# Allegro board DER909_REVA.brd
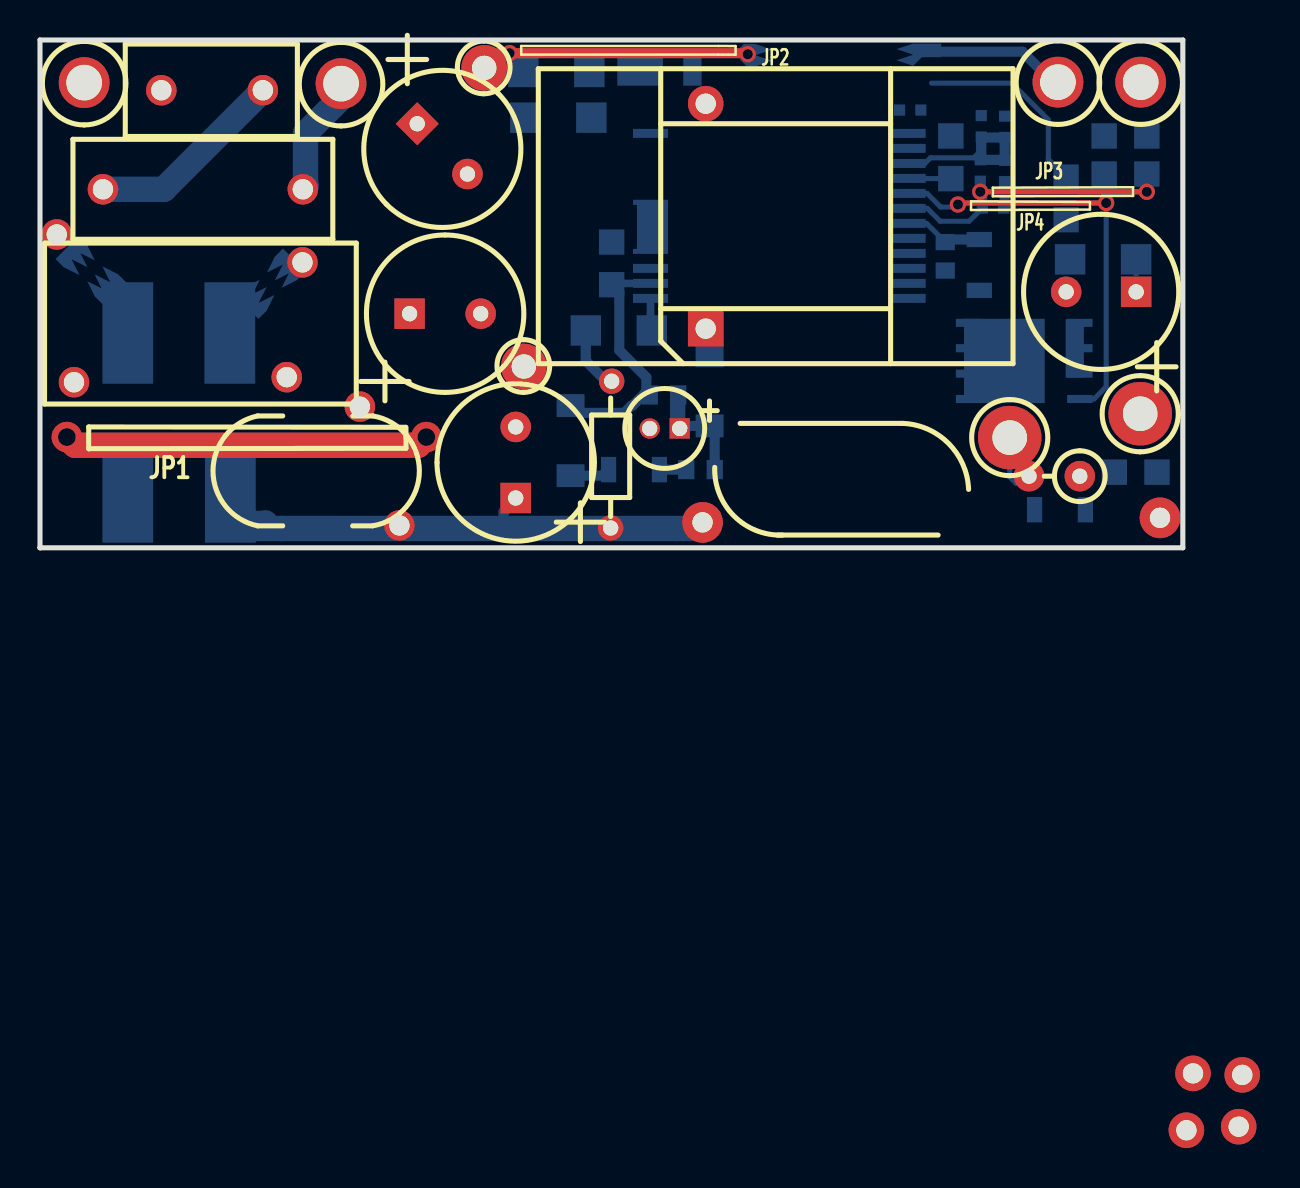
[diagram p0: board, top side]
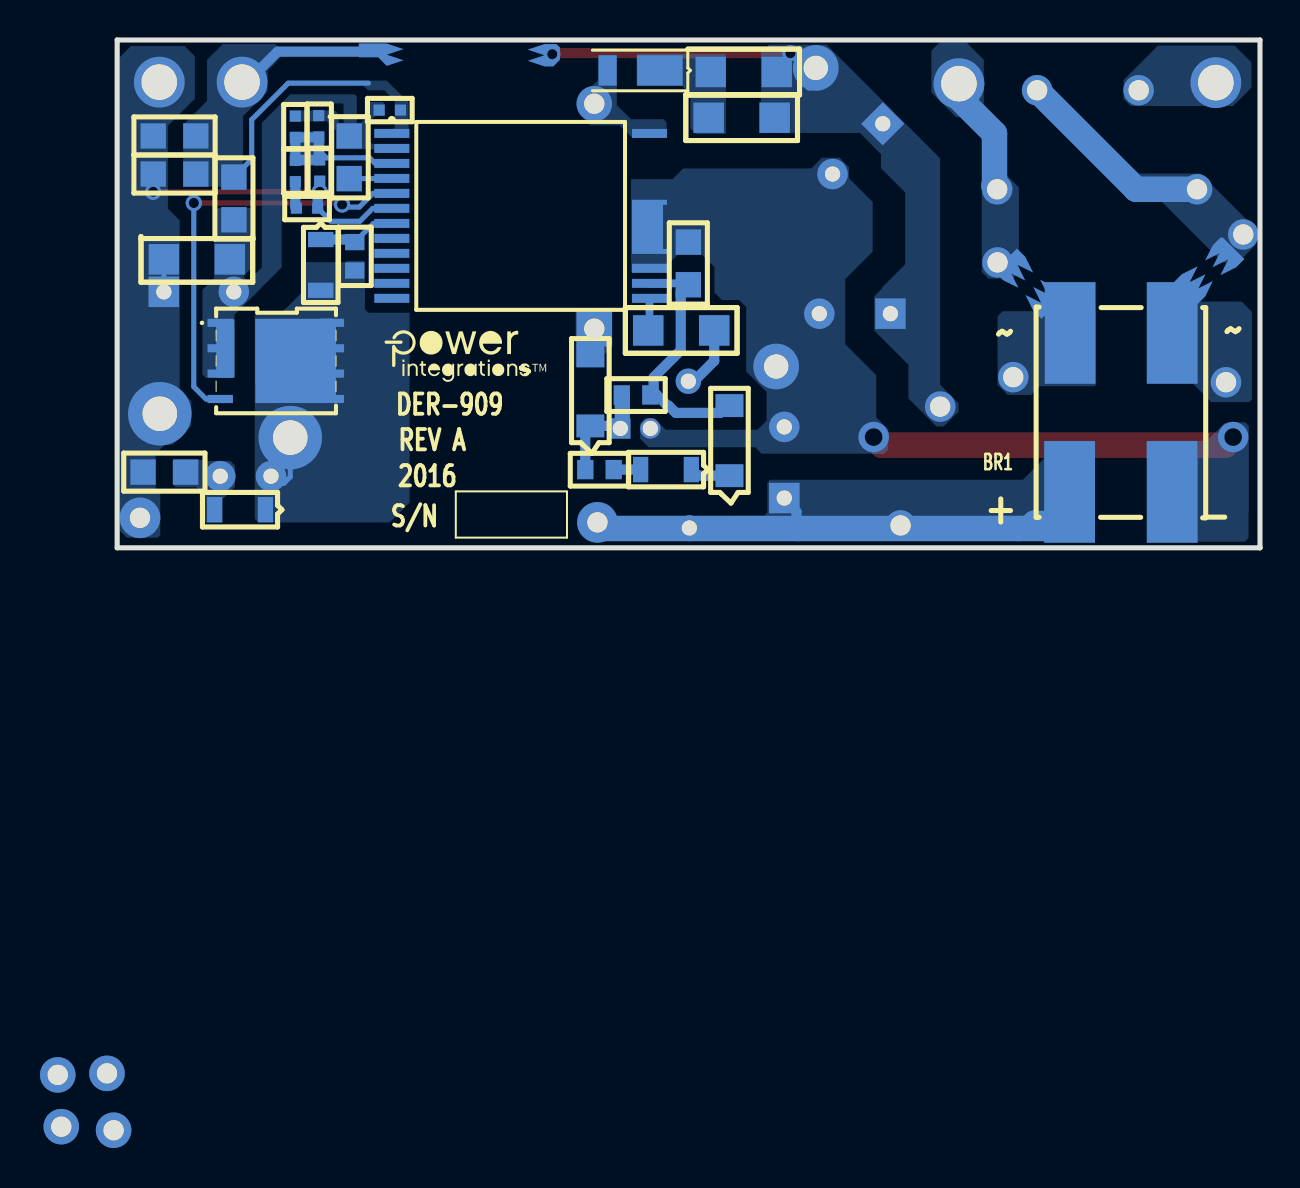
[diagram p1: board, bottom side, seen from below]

Outline 57.18 x 25.4 mm; copper layers: TOP, BOTTOM. Coordinates in mm from the lower left corner of the outline.
Outline path: 0,0 0,25.4 57.18,25.4 57.18,0 0,0 ; 0,0 0.03,0

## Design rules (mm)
constraint set DEFAULT: min track width 0.508

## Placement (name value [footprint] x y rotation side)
BR1  Z4DGP408L-HF  [PI_SM_D_Z4D]  9.5 2.74 0 bottom
C1  0.1 uF  [PINPXCAPRAD5X13X11P1MM040]  3.15 17.93 0 top
C2  22 uF  [PIPOLCAPCLYD320LS140030]  23.8 2.49 90 top
C3  22 uF  [PIPOLCAPCLYD320LS140030]  18.87 21.21 315 top
C4  22 uF  [PIPOLCAPCLYD320LS140030]  18.49 11.71 0 top
C5  2.2 nF  [PISMC1206]  24.28 21.51 0 bottom
C6  22 uf  [PIPOLCAP4P0X11P0XLS1P5D030]  32 5.97 180 top
C7  4.7 uF  [PISMC0805]  28.6 13.16 90 bottom
C8  1 nF  [PISMC0805]  53.75 3.78 0 bottom
C9  330 uF  [PIPOLCAPCYLD315LS138D030]  54.84 12.8 180 top
C10  2.2 uF  [PISMC0805]  45.57 20.6 270 bottom
C11  2.2 uF  [PISMC1206]  51.54 14.43 0 bottom
C12  1000 pF  [PISMR0402]  44.07 21.89 180 bottom
C13  330 pF  [PISMC0402]  47.09 20.55 90 bottom
C14  DNP  [PISMC0402]  48.26 18.31 90 bottom
C15  22 uF  [PISMC0805]  55.37 20.6 180 bottom
C16  22 uF  [PISMC0805]  55.37 18.69 180 bottom
C17  680 pF  [PINPCAPRAD394X275394030]  34.98 4.75 0 top
D1  DFLR1800-7  [PISMDDFLR120012]  30 23.88 180 bottom
D2  UFM12PL-TP  [PI_SM_SOD-123_12]  33.5 6.1 90 bottom
D3  BAV19WS  [PISMSOD323]  28.45 3.91 0 bottom
D4  BAV19WS  [PISMSOD323]  49.76 1.9 0 bottom
D5  BAV19WS  [PISMSOD323]  46.99 15.42 270 bottom
F1  3.15 A  [PI_RST_MICROFUSE]  6.07 22.89 0 top
FL1  Hole_70mils  [PI_HOLE_70MIL]  55.04 6.68 0 top
FL2  Hole_70mils  [PI_HOLE_70MIL]  48.51 5.49 0 top
FL3  Hole_50mils  [PI_HOLE_50MIL]  24.21 9.07 0 top
FL4  Hole_50mils  [PI_HOLE_50MIL]  22.23 24 0 top
L2  10 uH  [PI2P10P5X6P5X5P0LSD60]  13.89 1.35 90 top
L3  10 mH  [PI_IND_4P_590X295LS394X177D060]  3.05 13.44 180 top
NOREF  -  []  0 25.4 0 top
NOREF#2  -  []  -231.19 -154.89 0 top
NOREF#3  -  []  0.08 -0.03 90 top
NOREF#4  -  []  -153.38 44.12 0 top
NOREF#5  -  []  44.35 10.77 180 bottom
Q1  AON6220  [PISMPQFN5X6B]  52.02 11.25 270 bottom
R1  2 M  [PI18WVRESD80LS100D030]  28.6 8.33 270 top
R2  1.80 M  [PISMR1206]  30.61 10.87 180 bottom
R3  330 k  [PISMR1206]  24.18 23.8 0 bottom
R4  5.6 k  [PISMR0603]  31.93 7.65 180 bottom
R5  47  [PISMR0603]  33.76 3.91 180 bottom
R6  5.1  [PI14WVRESD100LS100D030]  52.02 3.58 180 top
R7  300  [PISMR0603]  45.29 13.87 90 bottom
R8  169.0 k  [PISMR0402]  47.04 18.34 90 bottom
R9  DNP  [PISMR0402]  47.14 16.99 0 bottom
R10  11.3 k  [PISMR0402]  48.26 21.59 270 bottom
R11  0.013  [PISMR0805]  51.33 16.41 90 bottom
T1  ATQ23.7/14  [PI_BOBBIN_ATQ23_7_H_6P]  36.8 16.59 90 top
TP1  WHT  [PITPKEYSTONE125X125]  2.21 23.27 0 top
TP2  BLK  [PITPKEYSTONE125X125]  15.06 23.22 0 top
TP3  RED  [PITPKEYSTONE125X125]  55.07 23.29 0 top
TP4  BLK  [PITPKEYSTONE125X125]  50.93 23.29 0 top
U1  INN3679C-H606  [PI_IC_INSOP_24D]  43.43 20.73 180 bottom
VR1  MMSZ5242B-7-F  [PI_SM_SOD-123_12]  26.54 3.61 90 bottom

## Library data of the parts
BR1 = DISCRETE BRIDGE_+~~-: room: 1
C1 = CAP NP: alternate symbols: (pinpxcaprad5x13x11p1mm040h)
C2-C4 = CAP POL: alternate symbols: (pipolcapclyd320ls140d30h750)
C5 = CAP NP_0: room: 1
C6 = CAP POL: alternate symbols: (pipolcap4p0x12p5xls1p5d030h); room: 1
C7 C11 C15 C16 = CAP NP: room: 2
C8 = CAP NP: alternate symbols: (pismc0805_1); room: 2
C9 = CAP POL: alternate symbols: (pipolcapcyld315ls138d030h); room: 2
C10 = CAP NP_0: room: 2
C12-C14 = CAP NP: alternate symbols: (pismr0402_1); room: 2
C17 = CAP NP: alternate symbols: (pinpycaprad500x220ls400040); room: 2
D1-D3 = DIODE: room: 1
D4 = DIODE: room: 2
D5 = DIODE
F1 = FUSE: alternate symbols: (pirstmicrofusehoz); room: 1
FL1 FL2 = FlyingLead: room: 2
FL3 FL4 = FlyingLead
L2 = INDUCTOR
L3 = INDUCTOR_4P_revD
Q1 = FET_N_SGD_123_4_5678: room: 2
R1 = R: alternate symbols: (pi18wresd080ls300d030); room: 1
R2-R5 = R: room: 1
R6 = R: alternate symbols: (pi14wvresd100ls125d030,pi14wvresd100ls150d030,pi14wvresd100ls200d030,pi14wvresd100ls300d030,pi14wresd100ls400d030,pi14wresd100ls500d030); room: 2
R7 R8 R10 = R: room: 2
R9 = R: alternate symbols: (pismr0402_1); room: 2
R11 = R
T1 = BATQ23_7_6P/GENERIC
TP1-TP4 = TESTPOINT
U1 = Inno3EP_0
VR1 = DIODE_ZENER: room: 1

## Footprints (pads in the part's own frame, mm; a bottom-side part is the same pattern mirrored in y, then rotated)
PI2P10P5X6P5X5P0LSD60
  round 1.524 hole 1.016: 1(-0.229,-4.089) 2(5.715,-2.108)
PI14WVRESD100LS100D030
  round 1.524 hole 0.762: 1(0,0) 2(2.54,0)
PI18WVRESD80LS100D030
  round 1.27 hole 0.762: 1(0,0) 2(7.341,-0.051)
PI_BOBBIN_ATQ23_7_H_6P
  rect 1.778x1.778 hole 1.016: 1(-5.626,3.5)
  round 1.778 hole 1.016: 2(-42.951,-23.343) 3(-42.875,-20.879) 4(-45.542,-23.165) 5(-45.72,-20.549) 6(5.626,3.5)
PI_HOLE_50MIL
  round 2.286 hole 1.219: 1(0,0)
PI_HOLE_70MIL
  round 3.175 hole 1.727: 1(0,0.025)
PI_IC_INSOP_24D
  rect 1.75x0.45 smd: 1(0,0) 2(0,-0.749) 3(0,-1.501) 4(0,-2.25) 5(0,-3) 6(0,-3.749) 7(0,-4.501) 8(0,-5.25) 9(0,-5.999) 10(0,-6.749) 11(0,-7.501) 12(0,-8.25) 13(12.89,-8.25) 14(12.89,-7.501) 15(12.89,-6.749) 24(12.89,0)
  custom 0.437x0.437 smd: 16(12.89,-4.671)
PI_IND_4P_590X295LS394X177D060
  round 1.524 hole 1.016: 1(2.21,-2.235) 2(1.346,5.156) 3(-9.296,4.902) 4(-10.084,-0.838)
PI_RST_MICROFUSE
  round 1.524 hole 1.016: 1(0,0) 2(5.08,0)
PI_SM_D_Z4D
  rect 2.54x5.08 smd: 1(0.025,-0.051) 2(0,-8.001) 3(-5.105,-8.001) 4(-5.105,-0.051)
PI_SM_SOD-123_12
  rect 1.143x1.397 smd: 1(0,0) 2(3.505,0)
PINPCAPRAD394X275394030
  round 2.032 hole 1.016: 1(-1.829,-3.48) 2(21.057,-3.251)
PINPXCAPRAD5X13X11P1MM040
  round 1.524 hole 1.016: 1(0,0) 2(10,0)
PIPOLCAP4P0X11P0XLS1P5D030
  rect 1.016x1.016 hole 0.762: 1(0,0)
  round 1.016 hole 0.762: 2(1.501,0)
PIPOLCAPCLYD320LS140030
  rect 1.524x1.524 hole 0.762: 1(0,0)
  round 1.524 hole 0.762: 2(3.556,0)
PIPOLCAPCYLD315LS138D030
  rect 1.524x1.524 hole 0.762: 1(0,0)
  round 1.524 hole 0.762: 2(3.5,0)
PISMC0402
  rect 0.559x0.559 smd: 1(0,0) 2(1.067,0)
PISMC0805
  rect 1.27x1.27 smd: 1(0,0) 2(2.134,0)
PISMC1206
  rect 1.524x1.524 smd: 1(0,0) 2(3.302,0)
PISMDDFLR120012
  rect 2.286x1.524 smd: 1(-0.025,0)
  rect 0.914x1.524 smd: 2(-2.642,0)
PISMPQFN5X6B
  rect 0.406x1.27 smd: 1(0,0) 2(1.27,0) 3(2.54,0) 4(3.81,0)
  rect 0.406x1.219 smd: 5(3.81,5.588) 6(2.54,5.588) 7(1.27,5.588) 8(0,5.588)
PISMR0402
  rect 0.559x0.559 smd: 1(0,0) 2(1.067,0)
PISMR0603
  rect 0.813x0.965 smd: 1(0,0) 2(1.422,0)
PISMR0805
  rect 1.27x1.27 smd: 1(0,0) 2(2.134,0)
PISMR1206
  rect 1.524x1.524 smd: 1(0,0) 2(3.302,0)
PISMSOD323
  rect 0.762x1.27 smd: 1(0,0) 2(2.54,0)
PITPKEYSTONE125X125
  round 2.54 hole 1.778: 1(0,0)

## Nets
GND: C9.2 C10.1 C11.1 C12.1 C13.2 Q1.1 Q1.2 Q1.3(S3) R10.1 R11.1 U1.2
GND_SIGNAL: C12.2 C15.2 C16.2 R11.2 TP4.1 U1.1
VBUS_IN: C8.2 C9.1 C11.2 C15.1 C16.1 C17.2 FL1.1 R8.1 R9.1 TP3.1 U1.6
D: D4.1 D5.2 FL2.1 Q1.5 Q1.6 Q1.7 Q1.8 R6.2 R7.1
NC8: U1.8
NC9: U1.9
NC10: U1.10
NC11: U1.11
NC12: U1.12
V-PIN: R2.1 U1.13(VPIN)
N10479111: F1.1 TP1.1
N10805923: BR1.4 C2.2 C3.2 C4.2 C6.2 C7.2 FL3.1 U1.15 U1.16
N10806149: C7.1 R4.2 U1.14 VR1.2
N10809540: Q1.4 U1.5
N10813018: R1.1 R2.2
N10840366: C3.1 C4.1 C5.1 FL4.1 L2.2 R3.1
N10873526: D5.1 R7.2 U1.7
N10897256: C13.1 C14.2 R8.2 R10.2 U1.3
N10950053: C6.1 D2.1 R4.1 R5.1
N10966650: D1.2 T1.6 U1.24
N11058959: BR1.1 C2.1 C17.1 L2.1 R1.2
N11077448: D3.2 R5.2
N11099981: C1.1 F1.2 L3.1
N11100013: C1.2 L3.4 TP2.1
N11100025: BR1.3(AC2) L3.2
N11100037: BR1.2 L3.3
N11105885: D2.2 T1.1
N11139601: C5.2 D1.1 R3.2
N11156493: C8.1 D4.2 R6.1
N11473834: D3.1 VR1.1
N11479585: C14.1 R9.2
N11512145: C10.2 U1.4

Pads without a net: T1 2 3 4 5

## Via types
v1: diameter 0.813, hole 0.508, TOP to BOTTOM, 6 vias
v2: diameter 1.524, hole 0.889, TOP to BOTTOM, 2 vias

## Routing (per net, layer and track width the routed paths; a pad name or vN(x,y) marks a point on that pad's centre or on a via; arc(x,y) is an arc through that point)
GND_SIGNAL: length 17.2
  BOTTOM w0.254: R11.2 50.44,19.43 50.44,21.41 48.62,23.24 44.6,23.24
  BOTTOM w0.508: 50.75,23.22 49.15,24.82 44.07,24.82
VBUS_IN: length 17.1
  TOP w0.254: v1(55.37,17.81) v1(47.04,17.81)
  BOTTOM w0.254: R9.1 46.48,16.33 45.03,16.33 44.39,16.98 U1.6 ; C16.1 55.32,18.64 55.32,17.86 v1(55.37,17.81) ; C11.2 C9.1 ; 47.07,17.78 47.07,18.31 R8.1
  BOTTOM w0.508: R9.1 47.14,17.7 v1(47.04,17.81) R8.1
D: length 3.4
  BOTTOM w0.254: 49.76,3.2 49.73,3.23 48.83,3.23 48.51,3.54 FL2.1
Net_7:
  vias: v1(35.41,24.69)
V-PIN: length 1.6
  BOTTOM w0.381: U1.13 30.54,10.93 R2.1
N10805923: length 18.3
  TOP w1.27: v2(1.35,5.54) 1.75,5.13 18.92,5.13 v2(19.33,5.54)
N10806149: length 12.7
  BOTTOM w0.381: C7.1 28.85,13.16 28.92,13.23 U1.14
  BOTTOM w0.508: 30.27,7.74 29.64,7.11 29.59,7.11 29.23,6.75 27.01,6.75 26.64,7.11 VR1.2 ; 30.27,7.74 30.37,7.65 R4.2 ; 30.27,7.74 30.34,7.8 30.34,8.52 28.98,9.88 28.98,12.78 C7.1
N10809540: length 21
  TOP w0.254: v1(53.34,17.25) 46.15,17.25 46.08,17.17 v1(45.92,17.17)
  BOTTOM w0.254: Q1.4 52.73,7.44 53.34,8.05 v1(53.34,17.25) ; v1(45.92,17.17) 45.8,17.04 45.06,17.04 44.38,17.73 U1.5
N10813018: length 3.2
  BOTTOM w0.508: R1.1 28.32,8.33 27.3,9.35 R2.2
N10840366: length 13.9
  TOP w0.508: 35.38,24.74 v1(23.5,24.74) 22.96,24.74 FL4.1
  BOTTOM w0.508: 22.53,23.22 22.5,23.19 ; C5.1 24,21.79 ; 22.5,23.14 22.53,23.11
N10873526: length 4
  BOTTOM w0.254: U1.7 44.35,16.23 R7.2
  BOTTOM w0.508: R7.2 45.42,15.42 D5.1
N10897256: length 11.5
  BOTTOM w0.254: U1.3 44.27,19.23 44.55,19.51 46.71,19.51 46.96,19.76 46.96,20.42 C13.1 ; R8.2 47.07,19.38 C14.2 ; 47.12,20.52 47.12,19.48 47.09,19.46
  BOTTOM w0.508: R8.2 48.23,19.41 C14.2 R10.2 47.12,20.52 C13.1 47.09,19.46
N10950053: length 5.6
  BOTTOM w0.508: C6.1 32.13,6.1 D2.1 33.76,5.84 R5.1
  BOTTOM w0.762: C6.1 31.9,6.07 31.9,7.62 R4.1
N11058959: length 29.6
  BOTTOM w0.508: 23.09,0.97 23.19,1.07 23.19,1.8 23.8,2.41 C2.1 ; R1.2 28.52,0.97 ; 11.28,1.24 11.35,1.17 11.86,1.17 12.06,0.97 ; 9.98,1.75 9.98,3.07 9.47,3.58 9.07,3.58
  BOTTOM w1.27: C17.1 32.84,0.97 10.77,0.97 10.52,1.22 ; 11.28,1.24 11.25,1.22 10.52,1.22 ; 10.52,1.22 9.98,1.75
N11077448: length 1.3
  BOTTOM w0.508: D3.2 R5.2
N11099981: length 10.1
  BOTTOM w1.27: F1.2 6.2,17.93 C1.1
N11100013: length 6.4
  BOTTOM w1.27: TP2.1 15.06,22.5 13.28,20.73 13.28,18.16 13.1,17.98 C1.2 13.32,18.1
N11473834: length 2
  BOTTOM w0.508: VR1.1 28.14,3.61 D3.1
N11479585: length 2.6
  BOTTOM w0.254: C14.1 48.29,18.29 48.29,17.07 48.26,17.04
  BOTTOM w0.508: C14.1 48.26,17.04 R9.2
N11512145: length 2.1
  BOTTOM w0.254: U1.4 43.44,18.47 C10.2

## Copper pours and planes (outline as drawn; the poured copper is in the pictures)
GND on BOTTOM (solid shape): 52.22,8.51 51.31,8.51 51.31,11.43 52.22,11.43
GND on BOTTOM: 49.94,14.02 50.61,13.35 50.63,13.35 50.85,13.56 50.85,13.59 50.34,14.1 50.34,16.94 50.39,16.99 52.04,16.99 52.07,17.02 52.32,16.76 52.32,13.49 52.93,12.88 52.93,8.69 52.76,8.51 51.36,8.51 51.31,8.56 51.31,11.66 48.95,14.02 48.95,21.77 48.93,21.78 48.93,21.91 48.62,22.22 45.9,22.22 45.85,22.17 45.85,21.26 45.87,21.23 46.02,21.23 46.1,21.31 46.1,21.69 46.28,21.87 48.51,21.87 48.54,21.84 48.54,21.41 48.46,21.34 46.69,21.34 46.23,20.88 46.23,19.99 46.18,19.94 44.48,19.94 44.3,19.76 42.62,19.76 42.57,19.81 42.57,20.17 42.62,20.22 44.45,20.22 44.65,20.42 44.65,21.21 44.27,21.59 43.89,21.59 43.81,21.67 43.81,22.22 43.89,22.3 44.53,22.3 44.6,22.22 44.6,21.64 45.01,21.23 45.16,21.23 45.19,21.26 45.19,22.58 45.29,22.68 48.51,22.68 49.94,21.26
GND_SIGNAL on BOTTOM (solid shape): 45.09,24.54 44.12,24.54 43.69,24.1 42.85,24.38 43.69,24.66 42.85,24.94 43.69,25.22 45.09,25.22
GND_SIGNAL on BOTTOM: 44.27,20.52 42.6,20.52 42.6,22.28 43.69,23.37 44.86,23.37 44.86,23.11 44.64,22.9 44.64,22.89 43.81,22.89 43.28,22.35 43.28,21.03 43.38,20.93 44.27,20.93
GND_SIGNAL on BOTTOM: 50.88,18.06 53.87,18.06 53.87,21.16 52.68,22.35 52.68,24.41 51.89,25.2 49.28,25.2 49.02,24.94 49.02,24.51 49.25,24.28 49.25,24.26 49.66,23.85 49.66,23.83 49.64,23.81 49.64,22.82 50.88,21.59
VBUS_IN on BOTTOM: 53.8,25.1 56.49,25.1 57.05,24.54 57.05,0.86 56.69,0.51 55.14,0.51 55.02,0.64 55.02,2.69 55.24,2.92 55.24,4.7 54.86,5.08 54.84,5.08 54.76,5.16 54.41,5.16 53.47,6.1 53.47,7.34 54.05,7.92 54.05,16.38 54.64,16.97 54.64,21.11 53.34,22.4 53.29,22.4 53.29,24.59
D on BOTTOM (solid shape): 50.27,11.46 50.27,7.24 46.23,7.24 46.23,11.46 49.17,11.46
D on BOTTOM: 44.81,14.35 45.67,14.35 45.73,14.29 47.97,14.29 47.97,12.74 48.92,11.79 50.19,11.79 50.29,11.68 50.29,1.45 50.11,1.27 43.54,1.27 42.55,2.26 42.55,11.76 44.6,11.76 44.78,11.94 44.78,14.33
Net_7 on BOTTOM (solid shape): 36.63,24.92 35.79,24.64 36.63,24.36 35.79,24.08 35.36,24.08 35.03,24.41 35.03,25.04 35.05,25.04 35.2,25.2 35.79,25.2
N10479111 on BOTTOM: 5.11,25.12 1.27,25.12 0.43,24.28 0.43,23.01 1.35,22.1 6.48,22.1 6.83,22.45 6.83,23.39
N10805923 on BOTTOM: 29.39,18.44 31.47,18.44 31.47,14.48 31.46,14.47 31.46,13.83 31.37,13.74 29.69,13.74 29.69,14.1 29.13,14.66 27.91,14.66 27.29,14.03 27.29,12.76 26.92,12.4 26.06,12.4 25.7,12.04 25.7,8.81 24.69,7.8 24.69,6.35 25.13,5.91 29.73,5.91 30.3,6.48 30.73,6.48 31.01,6.2 31.01,5.46 30.58,5.03 25.26,5.03 24.94,4.71 18.8,4.71 18.59,4.91 18.59,5.92 19.2,6.53 19.2,8.64 20.75,10.19 20.75,13.44 19.38,14.81 19.38,17.3 20.56,18.48 20.56,19.04 21.03,19.51 21.92,19.51 22.45,18.97 28.85,18.97
N10805923 on BOTTOM: 1.75,6.25 1.5,6.25 1.47,6.27 0.74,6.27 0.56,6.1 0.56,1.75 0.57,1.74 0.57,0.5 0.76,0.3 5.51,0.3 5.64,0.43 5.64,5.31 5.59,5.36 2.64,5.36
N10840366 on BOTTOM: 21.69,25.17 24.56,25.17 24.97,24.77 24.97,20.78 23.6,20.78 23.57,20.75 20.02,20.75 19.42,20.15 19.42,20.14 18.96,19.68 18.96,18.99 17.75,17.78 17.75,14.17 18.92,13 18.92,12.95 19.3,12.57 19.3,10.87 17.59,9.16 17.59,7.47 16.19,6.07 15.82,6.07 15.09,6.81 15.09,7.24 16,8.15 16,19.48
N10897256 on BOTTOM: 46.81,20.83 48.51,20.83 48.54,20.8 48.54,19.1 46.84,19.1 46.79,19.15 46.79,20.8
N10966650 on BOTTOM: 32.18,22.15 32.18,24.64 33.02,24.64 33.1,24.56 33.1,23.42 33.86,22.66 33.86,21.46 33.83,21.46 33.5,21.13 32.03,21.13 31.39,20.5 29.69,20.5 29.69,21.29 29.84,21.44 31.47,21.44
N11058959 on BOTTOM: 8.26,0.36 26.67,0.36 26.87,0.56 26.87,1.04 26.31,1.6 24.82,1.6 24.65,1.77 24.65,3.26 24.51,3.4 11.86,3.4 10.82,4.44 10.82,5.33 8.26,5.33
N11099981 on BOTTOM (solid shape): 2.36,15.14 2.74,14.38 2.02,14.73 2.37,14.03 1.58,14.43 1.98,13.64 1.19,14.03 0.97,14.25 0.79,14.44 0.79,14.45 1.85,15.52 1.98,15.52
N11099981 on BOTTOM: 2.97,18.72 0.23,15.98 0.23,15.14 1.09,14.27 1.88,14.27 4.91,17.31 6.08,17.31 6.43,17.65 6.43,18.67 6.38,18.72
N11100013 on BOTTOM (solid shape): 13.23,13.89 13.23,13.77 12.85,13.39 12.09,13.01 12.45,13.72 11.75,13.37 12.14,14.16 11.35,13.77 11.75,14.56 11.97,14.78 12.15,14.96 12.17,14.96
N11100013 on BOTTOM: 12.4,13.46 12.06,13.79 12.06,18.03 13.08,19.05 13.64,19.05 13.72,18.97 13.72,18.54 13.92,18.34 13.92,13.79 13.59,13.46
N11100013 on BOTTOM: 13.82,24.41 14.71,25.3 16,25.3 16.45,24.85 16.45,22.78 15.2,21.54 14.02,21.54 13.82,21.74
N11100025 on BOTTOM (solid shape): 3.92,13.68 4.14,13.46 4.32,13.27 4.32,13.26 3.25,12.19 3.12,12.19 2.74,12.57 2.36,13.34 3.08,12.98 2.73,13.68 3.52,13.28 3.13,14.07
N11100025 on BOTTOM: 5.64,8.26 3.4,8.26 2.44,7.29 0.53,7.29 0.41,7.42 0.41,11.81 0.91,12.32 5.61,12.32 5.64,12.29
N11100037 on BOTTOM (solid shape): 10.64,12.69 11.34,13.04 10.94,12.25 11.73,12.65 11.34,11.86 11.12,11.64 10.94,11.46 10.92,11.46 9.86,12.52 9.86,12.65 10.24,13.03 11,13.41
N11100037 on BOTTOM: 8.23,11.84 8.2,11.81 8.2,8.15 8.28,8.08 11.02,8.08 11.46,7.65 12.62,7.65 13.13,8.15 13.13,11.58 12.88,11.84
N11105885 on BOTTOM: 34.24,11.79 34.24,9.07 34.19,9.02 32.79,9.02 32.79,9.68 32.41,10.06 32.41,11.86 34.16,11.86
N11139601 on BOTTOM: 31.11,24.71 26.8,24.71 26.72,24.64 26.72,20.7 28.22,20.7 28.5,20.98 28.5,22.68 28.98,23.16 31.19,23.16 31.19,24.64
N11156493 on BOTTOM: 52.7,1.24 51.92,1.24 51.92,2.41 51.28,3.05 51.28,4.11 51.51,4.34 52.88,4.34 52.93,4.39 54.36,4.39 54.41,4.34 54.41,3.2 54.23,3.02 53.21,3.02 52.91,2.72 52.91,1.45

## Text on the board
Ref Des/Silkscreen Bottom: REV A | 2016 | DER-909 | S/N
Ref Des/Silkscreen Top: JP2 | JP4 | JP3 | JP1
User.5: 14.  FAB HOUSE LOGO,DATE CODE TO BE IN SILK SCREEN ONLY.DO NOT USE COPPER. | 13.  MATERIAL FR4 COPPER 2oz THICKNESS 0.062" | PLEASE DELETE THESE PINS
User.8: FIGURE | FINISHED_SIZE | 20.0 | 30.0 | 35.0 | 40.0 | 48.0 | 68.0 | 70.0 | DRILL CHART: TOP to BOTTOM | ALL UNITS ARE IN MILS | TOLERANCE_DRILL | +0.0/-0.0 | +3.0/-3.0 | PLATED | QTY | 6 | 8 | 2 | 10 | 4
